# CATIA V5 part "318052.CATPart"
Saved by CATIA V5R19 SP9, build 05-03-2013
Part number: 318052
Source: Unknown
Bounding box of the stored display mesh (mm): x 133 to 250, y 104 to 107, z 509.556 to 594
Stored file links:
  D:\16-SIL\kale oto\R19_V1\318052.CATPart
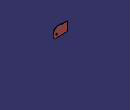
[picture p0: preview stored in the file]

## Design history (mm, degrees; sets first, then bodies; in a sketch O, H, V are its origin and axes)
Body1 "157\\123\\MANIFOLD_SOLID_BREP #73462" (main body)
  Solid1: solid without history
